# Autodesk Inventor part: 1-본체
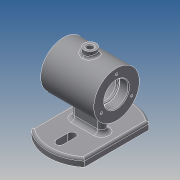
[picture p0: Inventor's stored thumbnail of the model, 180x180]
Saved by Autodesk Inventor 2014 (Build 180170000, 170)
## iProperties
Created: 2017-12
Part Number: 1-본체
Material: Generic
Document SubType Name: Modeling
Designer: kb542-16
Density: 1 g/cm^3
Appearance: Default
Author: kb542-16
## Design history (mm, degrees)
sketch "스케치1"
  geometry: L1 (0, 55)-(0, -55); L2 (-35, 42.426)-(-35, -42.426); L3 (35, 42.426)-(35, -42.426); A1 r 55 centre (0, 0) between (0, 55) and (0, -55); 2 further points
  constraints: 6 end point, 6 point on circle, 2 coincident, 2 parallel, 1 centre point, 1 midpoint, 1 vertical
  dimensions: "d0" = 55 radius of A1; "d1" = 35 distance from line of L2 point (0, 0); "d2" = 70 distance between parallel lines of L3 L2
extrude "돌출1" new body sketch "스케치1" distance "d3" = 10; taper "d4" = 0 deg
sketch "스케치2"
  geometry: L1 (-35, 42.426)-(-35, -42.426) reference; L2 (0, 40)-(0, 24); L3 (-5, 40)-(-5, 24); L4 (5, 24)-(5, 40); A1 r 55 centre (0, 0) between (-35, -42.426) and (35, -42.426) reference; A2 r 5 centre (0, 40) between (5, 40) and (-5, 40); A3 r 5 centre (0, 24) between (-5, 24) and (5, 24); 1 further point
  constraints: 8 end point, 4 point on circle, 4 tangent, 2 centre point, 2 parallel, 1 midpoint, 1 vertical alignment
  dimensions: "d5" = 16 distance of L2.start L2.end; "d6" = 5 radius of A2; "d7" = 24 distance of A1.centre L2.end
extrude "돌출2" cut sketch "스케치2" stored distance "d8" = 10; taper "d9" = 0 deg
sketch "스케치3"
  geometry: L1 (-35, 92)-(35, 92); L2 (35, 92)-(35, 62); L3 (35, 62)-(-35, 62); L4 (-35, 62)-(-35, 92); L5 (35, 0)-(-35, 0) reference; 3 further points
  constraints: 8 end point, 2 midpoint, 2 parallel, 1 horizontal, 1 perpendicular, 1 vertical alignment
  dimensions: "d10" = 62 distance between parallel lines of L5 L3; "d11" = 70 distance of L1.start L1.end; "d12" = 60 diameter of L1 L3
revolve "회전1" sketch "스케치3" stored, may be unused: angle "d13" = 90 deg
sketch "스케치4"
  geometry: L1 (35, 32)-(35, 92) reference; L2 (-35, 32)-(-35, 92) reference; L3 (-35, 92)-(35, 92) reference; L4 (-35, 32)-(35, 32) reference; L5 (-35, 78)-(-23.3, 78); L6 (-23, 77.7)-(-23, 76); L7 (-23, 76)-(-20.3, 76); L8 (-20, 76.3)-(-20, 84); L9 (-17, 87)-(17, 87); L10 (20, 84)-(20, 76.3); L11 (20.3, 76)-(23, 76); L12 (23, 76)-(23, 77.7); L13 (23.3, 78)-(35, 78); L14 (35, 78)-(35, 62); L15 (-35, 62)-(-35, 78); L16 (-35, 62)-(35, 62); L17 (35, 0)-(-35, 0) reference; L18 (-5, 10)-(5, 10) reference; L19 (20.3, 76)-(20, 76); L20 (20, 76)-(20, 76.3); L21 (-20.3, 76)-(-20, 76); L22 (-20, 76)-(-20, 76.3); A1 r 3 centre (17, 84) between (20, 84) and (17, 87); A2 r 3 centre (-17, 84) between (-17, 87) and (-20, 84); A3 r 0.3 centre (-23.3, 77.7) between (-23, 77.7) and (-23.3, 78); A4 r 0.3 centre (23.3, 77.7) between (23.3, 78) and (23, 77.7); 8 further points
  constraints: 32 end point, 10 point on line, 8 parallel, 8 point on circle, 8 tangent, 6 perpendicular, 4 centre point, 3 midpoint, 3 vertical alignment, 2 equal radius, 1 collinear
  dimensions: "d14" = 62 distance between parallel lines of L17 L16; "d15" = 32 diameter of L5 L16; "d16" = 28 diameter of L7 L16; "d17" = 50 diameter of L9 L16; "d18" = 28 diameter of L11 L16; "d19" = 32 diameter of L13 L16; "d22" = 40 distance of point (-20, 87) point (20, 87); "d23" = 3 radius of A1; "d65" = 3 distance between parallel lines of L10 L12; "d66" = 3 distance between parallel lines of L6 L8; "d67" = 0.3 radius of A3
revolve "회전2" sketch "스케치4" stored, may be unused: angle "d25" = 90 deg
sketch "스케치5"
  geometry: L1 (35, -42.426)-(35, 42.426) reference; L2 (-15, 0)-(15, 0); L3 (-15, -5)-(15, -5); L4 (15, 5)-(-15, 5); A1 r 55 centre (0, 0) between (-35, -42.426) and (35, -42.426) reference; A2 r 5 centre (-15, 0) between (-15, 5) and (-15, -5); A3 r 5 centre (15, 0) between (15, -5) and (15, 5); 1 further point
  constraints: 8 end point, 4 point on circle, 4 tangent, 2 centre point, 1 coincident, 1 midpoint, 1 parallel, 1 perpendicular
  dimensions: "d26" = 30 distance of L2.start L2.end; "d27" = 5 radius of A3
extrude "돌출3" join sketch "스케치5" stored distance "d28" = 0; taper "d29" = 0 deg
node "작업 평면1"
sketch "스케치6"
  geometry: C1 r 8 at (0, 0); 1 further point
  constraints: 1 centre point, 1 coincident
  dimensions: "d31" = 16 diameter of C1
extrude "돌출4" join sketch "스케치6" stored distance "d32" = 10; taper "d33" = 0 deg
sketch "스케치8"
  geometry: C1 r 8 at (0, 0) reference; C2 r 4 at (0, 0)
  constraints: 1 centre point, 1 coincident
  dimensions: "d41" = 8 diameter of C2
extrude "돌출5" cut sketch "스케치8" distance "d42" = 20; taper "d43" = 0 deg
sketch "스케치9" dims "d44" = 23
  geometry: L1 (0, 0)-(23, 0); C1 r 30 at (0, 0) reference; 1 further point
  constraints: 2 end point, 1 coincident, 1 horizontal alignment, 2 other
hole "구멍2" sketch "스케치9" at (23, 0) diameter "d45" = 3.242; stored, may be unused: countersink angle "d49" = 90 deg, drill point angle "d51" = 118 deg; dims "d46" = 8, "d47" = 4, "d48" = 2, "d50" = 10
node "작업 평면3"
sketch "스케치11"
  geometry: L1 (35, -62)-(-35, -62) reference; L2 (-35, 30)-(35, 30) reference; 2 further points
  constraints: 1 vertical alignment, 1 other
  dimensions: "d56" = 30 distance from line of point (0, 0) L2
feature "엠보싱1" sketch "스케치11" dims "d57" = 0.5, "d58" = 0
fillet "모깎기1" dims "d59" = 5
fillet "모깎기2" dims "d60" = 3
fillet "모깎기3" dims "d61" = 3
chamfer "모따기1" distance "d62" = 1; stored, may be unused: second distance "d63" = 2, angle "d64" = 45 deg
node "솔리드1"
mirror "대칭1"
pattern_circular "원형 패턴1" dims angle "d53" = 360 deg
mirror "대칭2"
node "투영된 루프1"
other parameters: "d30" = 99
